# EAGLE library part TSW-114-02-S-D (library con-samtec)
THROUGH-HOLE .025" SQ POST HEADER Source: Samtec TSW.pdf
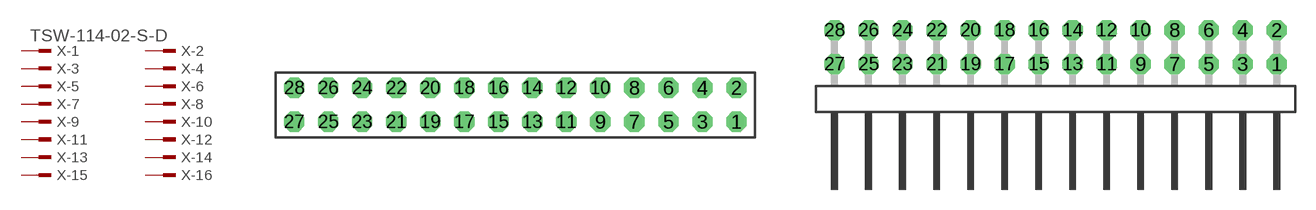
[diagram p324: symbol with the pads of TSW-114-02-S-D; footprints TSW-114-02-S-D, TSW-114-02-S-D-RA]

Designator prefix X; gates -1=MPINV -2=MPIN -3=MPIN -4=MPIN -5=MPIN -6=MPIN -7=MPIN -8=MPIN -9=MPIN -10=MPIN -11=MPIN -12=MPIN -13=MPIN -14=MPIN -15=MPIN -16=MPIN -17=MPIN -18=MPIN -19=MPIN -20=MPIN -21=MPIN -22=MPIN -23=MPIN -24=MPIN -25=MPIN -26=MPIN -27=MPIN -28=MPIN

## TSW-114-02-S-D (OC_FARNELL: unknown; OC_NEWARK: unknown)  [TSW-114-02-S-D]
1  -1:1  pas
2  -2:1  pas
3  -3:1  pas
4  -4:1  pas
5  -5:1  pas
6  -6:1  pas
7  -7:1  pas
8  -8:1  pas
9  -9:1  pas
10  -10:1  pas
11  -11:1  pas
12  -12:1  pas
13  -13:1  pas
14  -14:1  pas
15  -15:1  pas
16  -16:1  pas
17  -17:1  pas
18  -18:1  pas
19  -19:1  pas
20  -20:1  pas
21  -21:1  pas
22  -22:1  pas
23  -23:1  pas
24  -24:1  pas
25  -25:1  pas
26  -26:1  pas
27  -27:1  pas
28  -28:1  pas

## TSW-114-02-S-D-RA (OC_FARNELL: unknown; OC_NEWARK: unknown)  [TSW-114-02-S-D-RA]
Pads as for TSW-114-02-S-D

## Footprint TSW-114-02-S-D (pad centres in mm)
THROUGH-HOLE .025" SQ POST HEADER Source: Samtec TSW.pdf
drill 1 pad 1.5 octagon: 1 16.51,-1.27; 2 16.51,1.27; 3 13.97,-1.27; 4 13.97,1.27; 5 11.43,-1.27; 6 11.43,1.27; 7 8.89,-1.27; 8 8.89,1.27; 9 6.35,-1.27; 10 6.35,1.27; 11 3.81,-1.27; 12 3.81,1.27; 13 1.27,-1.27; 14 1.27,1.27; 15 -1.27,-1.27; 16 -1.27,1.27; 17 -3.81,-1.27; 18 -3.81,1.27; 19 -6.35,-1.27; 20 -6.35,1.27; 21 -8.89,-1.27; 22 -8.89,1.27; 23 -11.43,-1.27; 24 -11.43,1.27; 25 -13.97,-1.27; 26 -13.97,1.27; 27 -16.51,-1.27; 28 -16.51,1.27

## Footprint TSW-114-02-S-D-RA (pad centres in mm)
THROUGH-HOLE .025" SQ POST HEADER Source: Samtec TSW.pdf
drill 1 pad 1.5 octagon: 1 16.51,1.524; 2 16.51,4.064; 3 13.97,1.524; 4 13.97,4.064; 5 11.43,1.524; 6 11.43,4.064; 7 8.89,1.524; 8 8.89,4.064; 9 6.35,1.524; 10 6.35,4.064; 11 3.81,1.524; 12 3.81,4.064; 13 1.27,1.524; 14 1.27,4.064; 15 -1.27,1.524; 16 -1.27,4.064; 17 -3.81,1.524; 18 -3.81,4.064; 19 -6.35,1.524; 20 -6.35,4.064; 21 -8.89,1.524; 22 -8.89,4.064; 23 -11.43,1.524; 24 -11.43,4.064; 25 -13.97,1.524; 26 -13.97,4.064; 27 -16.51,1.524; 28 -16.51,4.064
